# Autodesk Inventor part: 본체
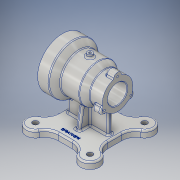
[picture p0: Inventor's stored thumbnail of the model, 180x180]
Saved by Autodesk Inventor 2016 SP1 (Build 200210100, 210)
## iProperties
Created: 2017-03
Part Number: 본체
Material: 알루미늄 6061
Document SubType Name: Modeling
Designer: Administrator
Density: 2.7 g/cm^3
Appearance: 알루미늄 - 평지
Mass: 958.762 g
Surface Area: 833.206 cm^2
Volume: 355.097 cm^3
Author: Administrator
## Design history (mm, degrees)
sketch "스케치1"
  geometry: L1 (45, 45)-(-45, 45); L2 (-45, 45)-(-45, -45); L3 (-45, -45)-(45, -45); L4 (45, -45)-(45, 45); L5 (45, 45)-(-45, -45); L6 (-45, 45)-(45, -45); C1 r 70 at (0, 0); 1 further point
  constraints: 12 end point, 4 midpoint, 2 parallel, 1 centre point, 1 horizontal, 1 perpendicular
  dimensions: "d0" = 90 distance of L3.end L2.end; "d1" = 90 distance of L2.end L1.end; "d2" = 140 diameter of C1
extrude "돌출1" new body sketch "스케치1" distance "d3" = 12; taper "d4" = 0 deg
sketch "스케치5"
  geometry: L1 (0, 0)-(49.497, -49.497); L2 (0, 0)-(49.497, 49.497); L3 (70, 0)-(-70, 0); L4 (0, -70)-(0, 70); C1 r 17 at (49.497, -49.497); C2 r 17 at (-49.497, -49.497); C3 r 17 at (49.497, 49.497); C4 r 17 at (-49.497, 49.497); A1 r 70 centre (0, 0) between (49.497, -49.497) and (49.497, 49.497); 1 further point
  constraints: 8 end point, 6 point on circle, 5 centre point, 3 symmetric about line, 2 coincident, 1 horizontal, 1 vertical, 3 other
  dimensions: "d14" = 140 diameter of A1; "d15" = 45 deg angle of L3 L1; "d16" = 45 deg angle of L2 L3; "d17" = 17 radius of C1
extrude "돌출2" join sketch "스케치5" distance "d19" = 12; taper "d20" = 0 deg
fillet "모깎기1" dims "d21" = 25
sketch "스케치6"
  geometry: L1 (45, -12.842)-(45, 12.842) reference; L2 (12.842, 45)-(-12.842, 45) reference; L3 (-45, 12.842)-(-45, -12.842) reference; L4 (-12.842, -45)-(12.842, -45) reference; C1 r 5 at (49.497, 49.497); C2 r 5 at (49.497, -49.497); C3 r 5 at (-49.497, -49.497); C4 r 5 at (-49.497, 49.497); A1 r 25 centre (70, 12.842) between (57.796, 34.661) and (45, 12.842) reference; A2 r 17 centre (49.497, 49.497) between (57.796, 34.661) and (34.661, 57.796) reference; A3 r 25 centre (12.842, 70) between (12.842, 45) and (34.661, 57.796) reference; A4 r 25 centre (-12.842, 70) between (-34.661, 57.796) and (-12.842, 45) reference; A5 r 17 centre (-49.497, 49.497) between (-34.661, 57.796) and (-57.796, 34.661) reference; A6 r 25 centre (-70, 12.842) between (-45, 12.842) and (-57.796, 34.661) reference; A7 r 25 centre (-70, -12.842) between (-57.796, -34.661) and (-45, -12.842) reference; A8 r 17 centre (-49.497, -49.497) between (-57.796, -34.661) and (-34.661, -57.796) reference; A9 r 25 centre (-12.842, -70) between (-12.842, -45) and (-34.661, -57.796) reference; A10 r 25 centre (12.842, -70) between (34.661, -57.796) and (12.842, -45) reference; A11 r 17 centre (49.497, -49.497) between (34.661, -57.796) and (57.796, -34.661) reference; A12 r 25 centre (70, -12.842) between (45, -12.842) and (57.796, -34.661) reference; 1 further point
  constraints: 4 centre point, 4 coincident, 3 equal radius
  dimensions: "d22" = 10 diameter of C1
extrude "돌출3" cut sketch "스케치6" stored distance "d23" = 12; taper "d24" = 0 deg
fillet "모깎기2" dims "d25" = 3
sketch "스케치7"
  geometry: L1 (-50, 82)-(50, 82); L2 (12.842, 0)-(-12.842, 0) reference; L3 (27, 109.5)-(15, 116.599); L4 (15, 116.599)-(9.806, 116.599); L5 (9.806, 116.599)-(-19, 116.599); L6 (-19, 116.599)-(-30, 127); L7 (-30, 127)-(-50, 127); L8 (-50, 127)-(-50, 82); L9 (27, 109.5)-(50, 109.5); L10 (50, 109.5)-(50, 82); 2 further points
  constraints: 18 end point, 3 horizontal, 2 perpendicular, 1 midpoint, 1 parallel, 1 vertical alignment
  dimensions: "d26" = 100 distance of L1.start L1.end; "d27" = 82 distance between parallel lines of L2 L1; "d28" = 90 diameter of L7 L1; "d29" = 20 distance of L6.end L7.end; "d30" = 31 horizontal distance of L5.end L7.end; "d31" = 65 horizontal distance of L3.end L7.end; "d62" = 23 distance of L3.start L9.end; "d63" = 55 diameter of L9 L1
revolve "회전1" sketch "스케치7" stored, may be unused: angle "d33" = 90 deg
sketch "스케치8"
  geometry: L1 (-50, 37)-(-50, 127) reference; L2 (-30, 37)-(-30, 127) reference; L3 (37.9, 47.401)-(37.9, 116.599) reference; L4 (50, 47.401)-(50, 116.599) reference; L5 (-19, 47.401)-(-19, 116.599) reference; L6 (15, 47.401)-(15, 116.599) reference; L7 (-50, 37)-(-50, 127) reference; L8 (-50, 82)-(50, 82); L9 (50, 47.401)-(50, 116.599) reference; L10 (50, 82)-(50, 99.5); L11 (20, 99.5)-(20, 108); L12 (50, 99.5)-(20, 99.5); L13 (20, 108)-(-27, 108); L14 (-27, 108)-(-27, 117); L15 (-27, 117)-(-50, 117); L16 (-50, 117)-(-50, 82); 1 further point
  constraints: 16 end point, 4 perpendicular, 2 midpoint, 2 point on line, 1 horizontal, 1 vertical
  dimensions: "d34" = 70 diameter of L15 L8; "d35" = 52 diameter of L13 L8; "d36" = 35 diameter of L12 L8; "d37" = 30 distance of L10.end L11.start; "d39" = 23 distance of L14.end L15.end; "d40" = 47 distance of L11.end L13.end (derived)
revolve "회전2" sketch "스케치8" stored, may be unused: angle "d41" = 90 deg
fillet "모깎기3" dims "d42" = 3
chamfer "모따기1" distance "d43" = 1; stored, may be unused: second distance "d44" = 2, angle "d45" = 45 deg
sketch "스케치9" dims "d46" = 80
  geometry: L1 (0, 0)-(-56.331, 0); C1 r 45 at (0, 0) reference; C2 r 36 at (0, 0) reference; 2 further points
  constraints: 2 end point, 1 coincident, 1 horizontal, 1 vertical alignment, 2 other
hole "구멍1" sketch "스케치9" at (0, 40) diameter "d47" = 3.242; stored, may be unused: countersink angle "d51" = 90 deg, drill point angle "d53" = 118 deg; dims "d48" = 9, "d49" = 4, "d50" = 2, "d52" = 11
sketch "스케치11" dims "d64" = 55
  geometry: L1 (0, 0)-(-49.31, -28.469); L2 (0, 0)-(0, 57.212); L3 (0, 0)-(47.893, -27.651); C1 r 7 at (0, 27.5); C2 r 29 at (0, 0) reference; C3 r 27.5 at (0, 0) reference; C4 r 26 at (0, 0) reference; C5 r 7 at (23.816, -13.75); C6 r 7 at (-23.816, -13.75); A1 r 27.5 centre (0, 0) between (23.816, -13.75) and (-23.816, -13.75) reference; 3 further points
  constraints: 6 end point, 3 centre point, 2 point on circle, 2 point on line, 1 coincident, 1 vertical, 1 vertical alignment, 2 other
  dimensions: "d65" = 7 radius of C1; "d71" = 120 deg angle of L1 L2; "d72" = 120 deg angle of L3 L2; "d73" = 7 radius of C5; "d74" = 7 radius of C6
extrude "돌출4" join sketch "스케치11" distance "d69" = 15; taper "d70" = 0 deg
sketch "스케치13"
  geometry: C1 r 17.5 at (0, -27.5) reference; A1 r 27.5 centre (0, -27.5) between (-19.573, -46.817) and (19.573, -46.817) reference; A2 r 7 centre (23.816, -41.25) between (19.573, -46.817) and (26.516, -34.792) reference; A3 r 27.5 centre (0, -27.5) between (26.516, -34.792) and (6.943, -0.891) reference; A4 r 7 centre (0, 0) between (6.943, -0.891) and (-6.943, -0.891) reference; A5 r 27.5 centre (0, -27.5) between (-6.943, -0.891) and (-26.516, -34.792) reference; A6 r 7 centre (-23.816, -41.25) between (-26.516, -34.792) and (-19.573, -46.817) reference; 2 further points
  constraints: 1 coincident
hole "구멍2" sketch "스케치13" at (0, 0) diameter "d75" = 3.242; stored, may be unused: countersink angle "d79" = 90 deg, drill point angle "d81" = 118 deg; dims "d76" = 9, "d77" = 4, "d78" = 2, "d80" = 11
sketch "스케치15"
  geometry: L1 (-37, -4)-(37, -4); L2 (37, -4)-(37, 4); L3 (37, 4)-(-37, 4); L4 (-37, 4)-(-37, -4); L5 (-37, -4)-(37, 4); L6 (37, -4)-(-37, 4); 1 further point
  constraints: 12 end point, 2 midpoint, 2 parallel, 1 horizontal, 1 perpendicular
  dimensions: "d85" = 74 distance of L3.end L2.end; "d86" = 8 distance of L1.end L2.end
extrude "돌출5" join sketch "스케치15" stored distance "d87" = 15; taper "d88" = 0 deg
sketch "스케치16"
  geometry: L1 (12, 12.842)-(12, 37.279) reference; L2 (9, -12.842)-(12, -12.842) reference; L3 (12, -12.842)-(12, -37.279) reference; L4 (9, -34.661)-(9, -12.842) reference; L5 (51.554, -16.434)-(12, -23.409); A1 r 34.599 centre (82, 0) between (47.633, -4) and (47.633, 4) reference; 2 further points; 1 other entity
  constraints: 2 end point, 1 point on circle, 1 point on line, 1 other
  dimensions: "d89" = 100 deg angle of L3 L5
feature "리브1" sketch "스케치16" dims "d90" = 1, "d91" = 8, "d92" = 0, "d93" = 0, "d94" = 1, "d95" = 1
fillet "모깎기4" dims "d96" = 3
node "작업 평면1"
sketch "스케치17"
  geometry: C1 r 5 at (0, 0); 1 further point
  constraints: 1 centre point, 1 coincident
  dimensions: "d99" = 10 diameter of C1
extrude "돌출6" join sketch "스케치17" stored distance "d100" = 15; taper "d101" = 0 deg
sketch "스케치18"
  geometry: 2 further points
  constraints: 1 coincident
hole "구멍3" sketch "스케치18" at (0, 0) diameter "d102" = 4.134; stored, may be unused: countersink angle "d106" = 90 deg, drill point angle "d108" = 118 deg; dims "d103" = 10, "d104" = 4, "d105" = 2, "d107" = 14.2
fillet "모깎기6" dims "d109" = 3
fillet "모깎기7" dims "d110" = 3
fillet "모깎기8" dims "d111" = 1
fillet "모깎기9" dims "d112" = 3
fillet "모깎기10" dims "d113" = 3
fillet "모깎기11" dims "d114" = 3
fillet "모깎기12" dims "d115" = 3
chamfer "모따기2" distance "d116" = 1; stored, may be unused: second distance "d117" = 2, angle "d118" = 45 deg
fillet "모깎기13" dims "d119" = 3
sketch "스케치19"
  geometry: L1 (12.842, 45)-(-12.842, 45) reference; L2 (45, -12.842)-(45, 12.842) reference; L3 (-12.842, -45)-(12.842, -45) reference; L4 (-45, 12.842)-(-45, -12.842) reference; L5 (-45, 0)-(45, 0); C1 r 5 at (-49.497, 49.497) reference; C2 r 5 at (49.497, -49.497) reference; C3 r 5 at (49.497, 49.497) reference; C4 r 5 at (-49.497, -49.497) reference; A1 r 25 centre (12.842, 70) between (12.842, 45) and (34.661, 57.796) reference; A2 r 17 centre (49.497, 49.497) between (57.796, 34.661) and (34.661, 57.796) reference; A3 r 25 centre (70, 12.842) between (57.796, 34.661) and (45, 12.842) reference; A4 r 25 centre (70, -12.842) between (45, -12.842) and (57.796, -34.661) reference; A5 r 17 centre (49.497, -49.497) between (34.661, -57.796) and (57.796, -34.661) reference; A6 r 25 centre (12.842, -70) between (34.661, -57.796) and (12.842, -45) reference; A7 r 25 centre (-12.842, -70) between (-12.842, -45) and (-34.661, -57.796) reference; A8 r 17 centre (-49.497, -49.497) between (-57.796, -34.661) and (-34.661, -57.796) reference; A9 r 25 centre (-70, -12.842) between (-57.796, -34.661) and (-45, -12.842) reference; A10 r 25 centre (-70, 12.842) between (-45, 12.842) and (-57.796, 34.661) reference; A11 r 17 centre (-49.497, 49.497) between (-34.661, 57.796) and (-57.796, 34.661) reference; A12 r 25 centre (-12.842, 70) between (-34.661, 57.796) and (-12.842, 45) reference; 2 further points
  constraints: 2 end point, 2 midpoint, 1 vertical alignment, 1 other
  dimensions: "d120" = 35 distance from line of point (0, -35) L5
feature "엠보싱1" sketch "스케치19" dims "d19" = 12, "d20" = 0, "d121" = 0.5, "d122" = 0
node "솔리드1"
pattern_circular "원형 패턴1" dims angle "d55" = 360 deg
pattern_circular "원형 패턴2" dims angle "d83" = 360 deg
mirror "대칭1"
node "투영된 루프2"
node "투영된 루프3"
node "투영된 루프4"
node "투영된 루프5"
node "투영된 루프6"
node "투영된 루프9"
node "투영된 루프10"
node "투영된 루프11"
other parameters: "d98" = 122
